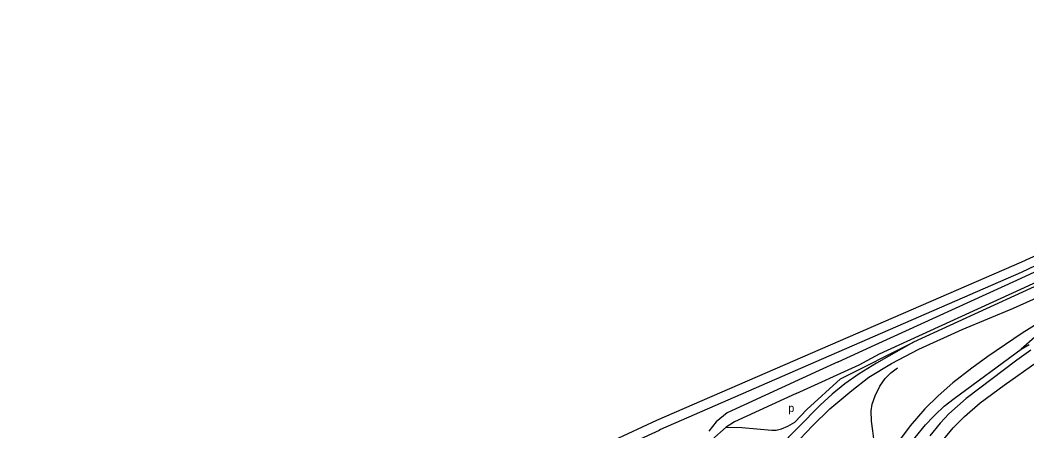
# Model space of a CAD drawing. Extents: x 154320 to 156262, y 382651 to 384180.
# Drawn here: x 154681 to 155184, y 383914 to 384120 of the extents above; entities that cross this region are included whole.
import ezdxf

# ---------------------------------------------------------------- set-up
doc = ezdxf.new("R2010")
doc.units = 0
for name, color, linetype in [('BLT_Basislijn', 7, 'Continuous'), ('BLT_Centroide', 7, 'Continuous'), ('BLT_Vlakafsluiter', 7, 'Continuous')]:
    doc.layers.add(name, color=color, linetype=linetype)

msp = doc.modelspace()

# ---------------------------------------------------------------- linework, layer by layer
at = {"layer": 'BLT_Basislijn'}
for p, q in [((155177.56, 383975.75), (155400, 384076.27)), ((155268.51, 384038.46), (155181.49, 383998.69)), ((155200.57, 384002.65), (155181.31, 383993.56)), ((155181.49, 383998.69), (154999.09, 383919.62)), ((155181.31, 383993.56), (155078.73, 383948.87)), ((155078.73, 383948.87), (155001.18, 383915.08)), ((155089.9, 383948.93), (155080.47, 383944.63)), ((155080.47, 383944.63), (155034.48, 383923.46)), ((155068.91, 383933.12), (155100.42, 383947.51)), ((155068.91, 383933.12), (155038.19, 383919.06)), ((154999.09, 383919.62), (154635.38, 383751.76)), ((155038.19, 383919.06), (155033.91, 383916.35)), ((155000.42, 383914.73), (154989.13, 383909.51)), ((155001.18, 383915.08), (155000.42, 383914.73)), ((155026.78, 383909.99), (155033.91, 383916.35))]:
    msp.add_line(p, q, dxfattribs=at)
for points in [[(155179.2, 383989.79), (155246.91, 384020.95), (155331.29, 384059.78), (155461.64, 384119.51)], [(155181.29, 383985.24), (155249, 384016.41), (155333.38, 384055.23), (155463.72, 384114.97)], [(155400, 384083.5), (155127.49, 383958.74)], [(155089.9, 383948.93), (155108.43, 383957.35), (155179.2, 383989.79)], [(155100.42, 383947.51), (155110.63, 383952.86), (155181.29, 383985.24)], [(155065.27, 383903.46), (155070.7, 383910.31), (155077.07, 383916.93), (155085.81, 383925.43), (155096.68, 383934.65), (155105.18, 383941.26), (155116.51, 383948.11), (155130.21, 383955.2), (155151.94, 383965.12), (155177.56, 383975.75)], [(155190.19, 383968.43), (155181.93, 383963.23), (155164.69, 383951.66), (155156.66, 383945.75), (155147.21, 383938.43), (155139.89, 383932.05), (155133.28, 383925.43), (155125.96, 383916.93), (155120.06, 383909.13), (155114.62, 383899.68), (155110.37, 383891.88), (155107.07, 383883.61), (155104.47, 383875.11), (155102.34, 383866.6), (155100.93, 383857.86)], [(155127.49, 383958.74), (155109.07, 383948.35), (155100.34, 383942.92), (155093.25, 383937.95), (155086.88, 383932.76), (155080.97, 383927.32), (155069.87, 383916.22), (155065.15, 383911.26), (155063.66, 383909.21)], [(155068.28, 383918.82), (155074.22, 383925.16), (155091.15, 383940.45), (155127.49, 383958.74)], [(155186.15, 383954.69), (155179.18, 383949.73), (155153.91, 383930.59), (155145.18, 383922.91), (155140.93, 383918.3), (155135.73, 383911.92)], [(155137.41, 383921.47), (155138.33, 383922.44), (155142.93, 383926.81), (155147.89, 383930.71), (155181.43, 383955.28)], [(155181.43, 383955.28), (155185.33, 383957.64)], [(155141.99, 383909.56), (155147.42, 383916.06), (155153.09, 383921.73), (155160.88, 383928.46), (155172.81, 383937.32), (155189.34, 383948.9)], [(155107.88, 383909.24), (155107.17, 383914.56), (155106.55, 383919.24), (155106.48, 383924.4), (155106.97, 383927.74), (155108.35, 383931.95), (155110.82, 383936.85), (155113.45, 383940.7), (155116.18, 383943.43), (155119.63, 383945.87)], [(155034.48, 383923.46), (155028.96, 383919.03), (155025.22, 383914.26)], [(155033.91, 383916.35), (155041.81, 383916.14), (155056.86, 383914.85), (155058.94, 383914.88), (155061.53, 383915.49), (155064.76, 383916.82), (155068.28, 383918.82)], [(155106.03, 383799.98), (155105.74, 383813.52), (155106.21, 383841.75), (155107.27, 383854.75), (155108.45, 383863.13), (155110.22, 383870.58), (155111.99, 383877.55), (155114.59, 383884.28), (155118.84, 383893.85), (155121.91, 383900.23), (155124.98, 383905.78), (155128.41, 383911.1), (155133.6, 383917.48), (155137.41, 383921.47)]]:
    msp.add_lwpolyline(points, dxfattribs=at)
at = {"layer": 'BLT_Vlakafsluiter'}
msp.add_line((155195.01, 383967.21), (155181.43, 383955.28), dxfattribs=at)

# ---------------------------------------------------------------- texts
at = {"layer": 'BLT_Centroide'}
msp.add_text('p', height=4, dxfattribs=at).set_placement((155065.03, 383923.91))

doc.saveas('drawing.dxf')
